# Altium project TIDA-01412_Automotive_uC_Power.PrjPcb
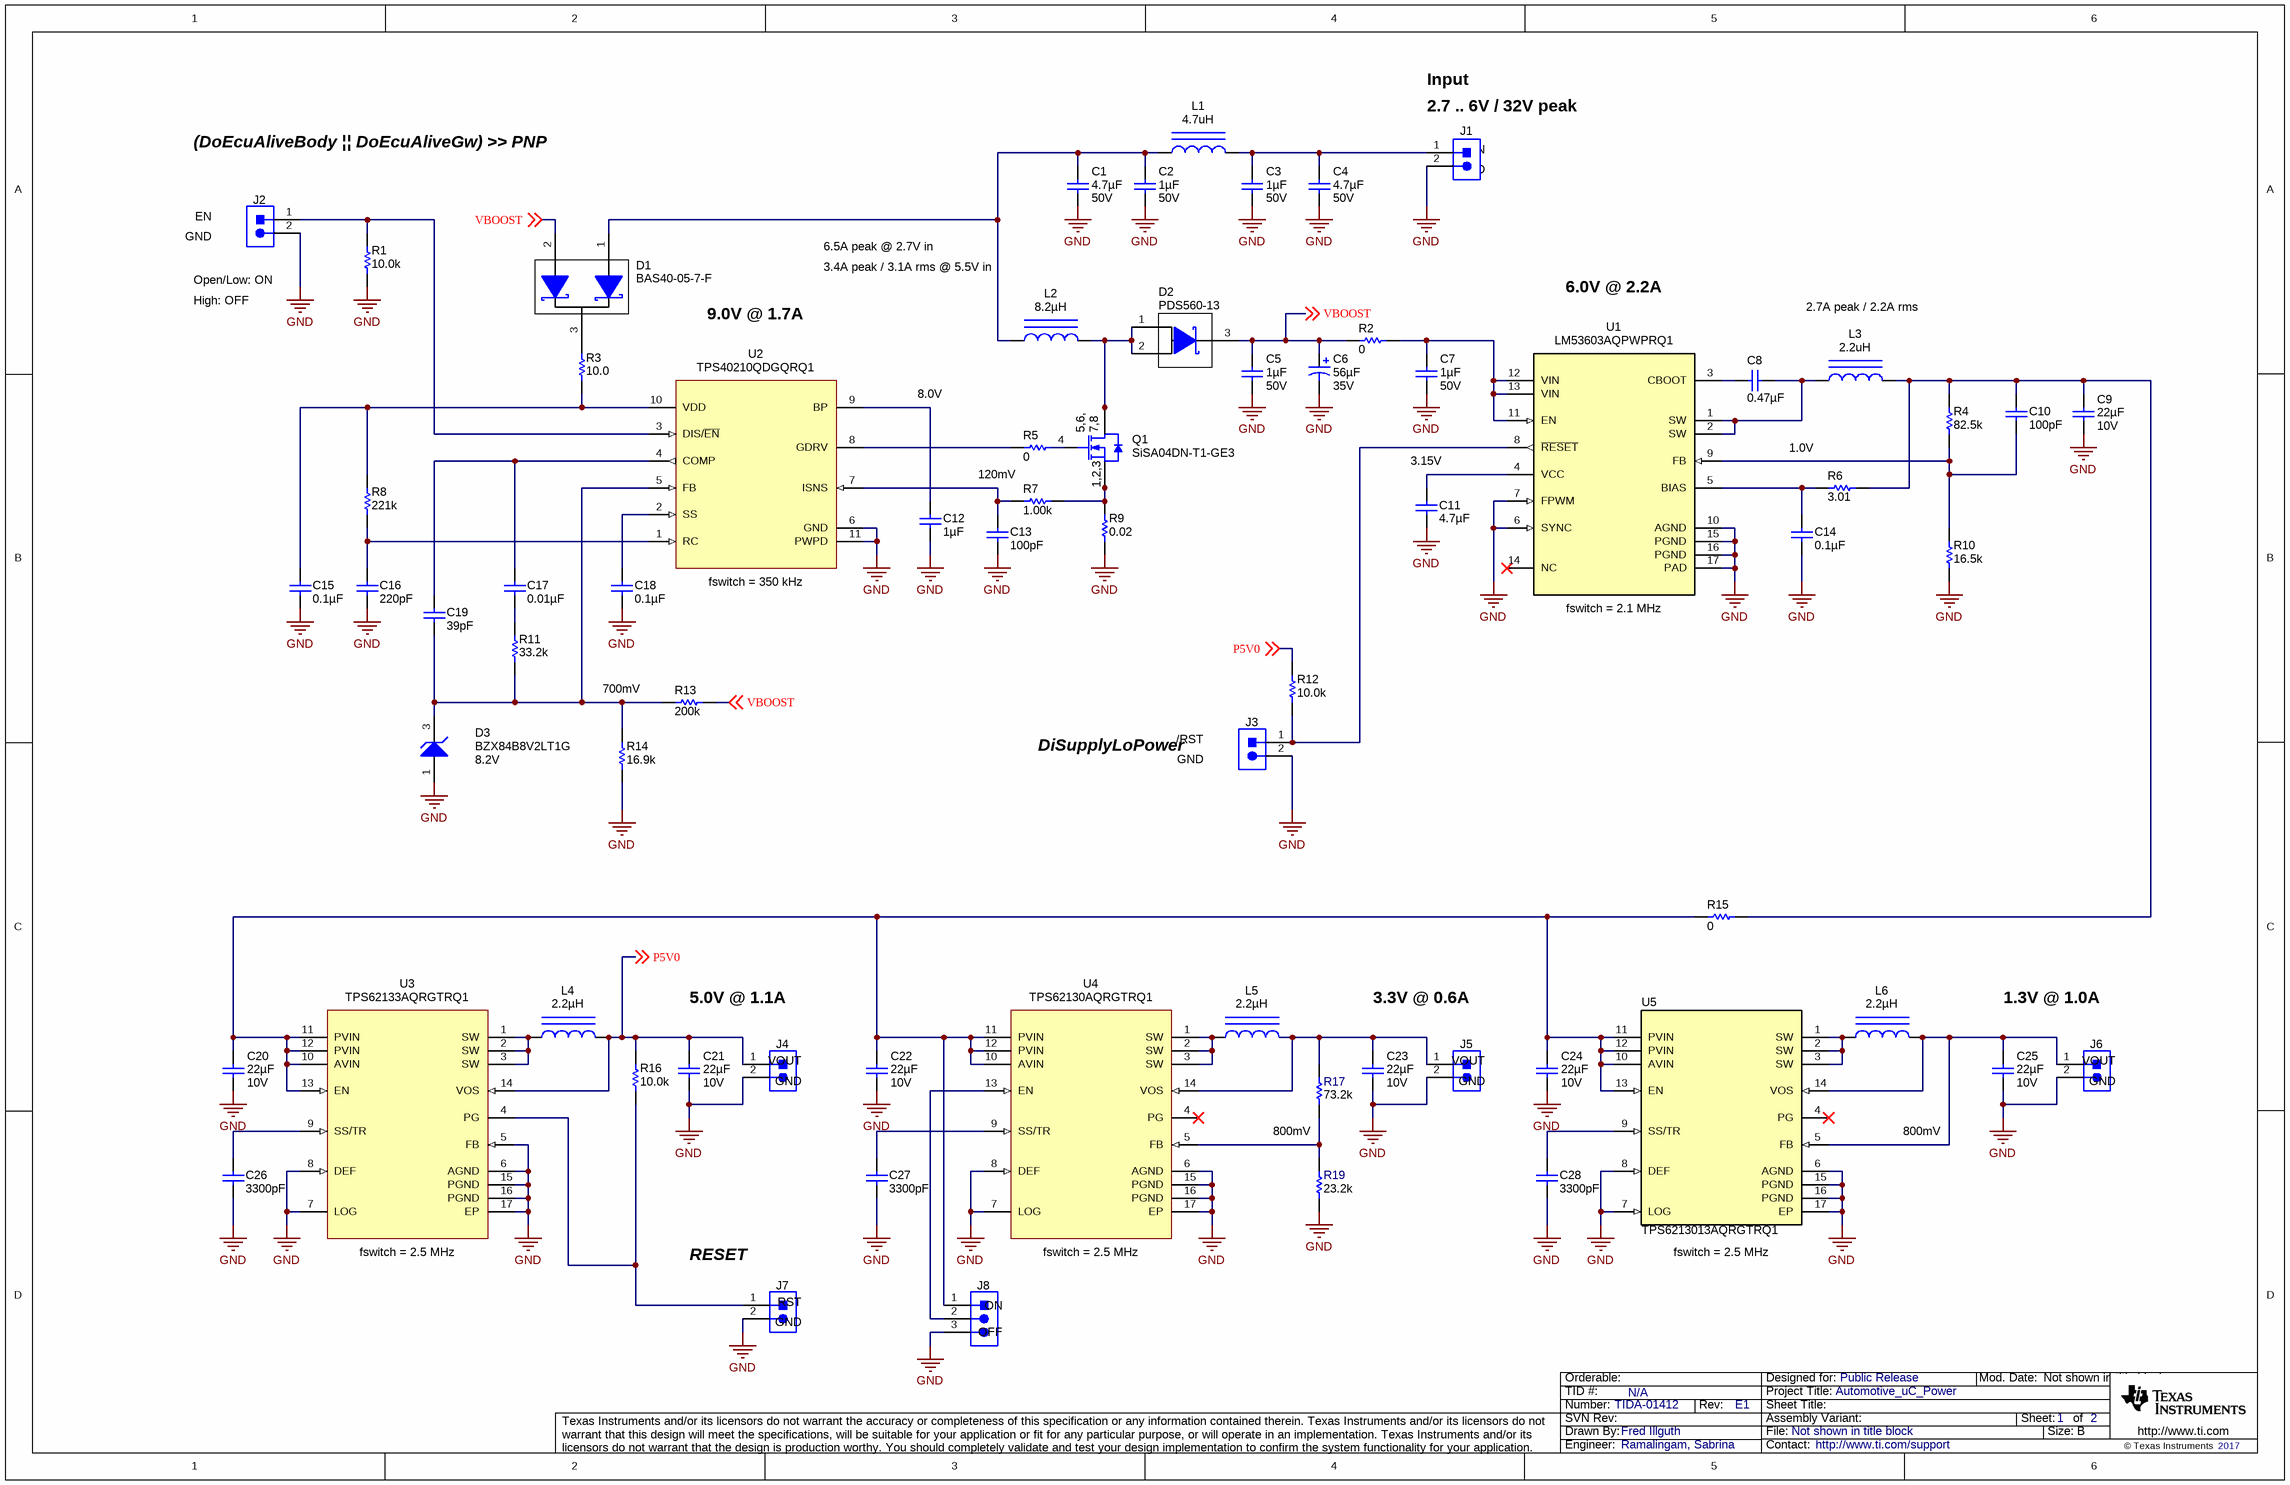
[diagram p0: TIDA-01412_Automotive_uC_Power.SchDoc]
CopyrightYear: 2017; PCB_Layout: Fred Illguth; PCB_Rev: E1; PRJ_Customer: Public Release; PRJ_Engineer: Ramalingam, Sabrina; PRJ_Number: TIDA-01412; PRJ_Title: Automotive_uC_Power; SCH_Rev: E1; TechSupport: http://www.ti.com/support; TID: N/A
2 sheets, 79 parts. Net scope: global (net labels, ports and power ports of the same name join across sheets).
Board file: TIDA-01412_Automotive_uC_Power.PcbDoc
Sheets:
  TIDA-01412_Automotive_uC_Power.SchDoc
  TIDA-01412_Automotive_uC_Power_Hardware.SchDoc

## Sheet TIDA-01412_Automotive_uC_Power.SchDoc
size 431 x 279 mm; Date: Not shown in title block; ApprovedBy: Not shown in title block; CheckedBy: Not shown in title block; Author: Not shown in title block; CompanyName: Not shown in title block; DrawnBy: Fred Illguth; Engineer: Not shown in title block; Organization: Not shown in title block; Address1: Not shown in title block; Address2: Not shown in title block; Address3: Not shown in title block; Address4: Not shown in title block; DocumentNumber: 1; Revision: Use project parameter SCH_Rev; SheetNumber: 1; SheetTotal: 2; PageSetup: Record=PageOptions¦CenterHorizontal=True¦CenterVertical=True¦PrintScale=1.00¦XCorrection=1.00¦YCorrection=1.00¦PrintKind=0¦BorderSize=5000000¦LeftOffset=0¦BottomOffset=0¦Orientation=2¦PaperLength=1000¦PaperWidth=1000¦Scale=100¦PaperSource=15¦PrintQuality=600¦MediaType=1¦DitherType=10¦PaperKind=Letter¦PrintScaleMode=1

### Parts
C1  ValueDisplayed: 4.7µF  Value2: 50V  [1210_270]  (hidden comment: GRM32ER71H475KA88L)
C2  ValueDisplayed: 1µF  Value2: 50V  [1206]  (hidden comment: GRM31MR71H105KA88L)
C3  ValueDisplayed: 1µF  Value2: 50V  [1206]  (hidden comment: GRM31MR71H105KA88L)
C4  ValueDisplayed: 4.7µF  Value2: 50V  [1210_270]  (hidden comment: GRM32ER71H475KA88L)
C5  ValueDisplayed: 1µF  Value2: 50V  [1206]  (hidden comment: GRM31MR71H105KA88L)
C6  ValueDisplayed: 56µF  Value2: 35V  [ZL_630x1100]  (hidden comment: 35ZL56MEFCTA6.3X11)
C7  ValueDisplayed: 1µF  Value2: 50V  [1206]  (hidden comment: GRM31MR71H105KA88L)
C8  ValueDisplayed: 0.47µF  [0603]  (hidden comment: GRM188R71E474KA12D)
C9  ValueDisplayed: 22µF  Value2: 10V  [1206_180]  (hidden comment: GCM31CR71A226KE02)
C10  ValueDisplayed: 100pF  [0603]  (hidden comment: GRM1885C1H101JA01D)
C11  ValueDisplayed: 4.7µF  [0805_HV]  (hidden comment: GRM21BR71A475KA73L)
C12  ValueDisplayed: 1µF  [0603]  (hidden comment: GRM188R71C105KA12D)
C13  ValueDisplayed: 100pF  [0603]  (hidden comment: GRM1885C1H101JA01D)
C14  ValueDisplayed: 0.1µF  [0603]  (hidden comment: GCM188R71H104KA57D)
C15  ValueDisplayed: 0.1µF  [0603]  (hidden comment: GCM188R71H104KA57D)
C16  ValueDisplayed: 220pF  [0603]  (hidden comment: GRM188R71H221KA01D)
C17  ValueDisplayed: 0.01µF  [0603]  (hidden comment: C0603X103K5RACTU)
C18  ValueDisplayed: 0.1µF  [0603]  (hidden comment: GCM188R71H104KA57D)
C19  ValueDisplayed: 39pF  [0603]  (hidden comment: GRM1885C1H390JA01D)
C20  ValueDisplayed: 22µF  Value2: 10V  [1206_180]  (hidden comment: GCM31CR71A226KE02)
C21  ValueDisplayed: 22µF  Value2: 10V  [1206_180]  (hidden comment: GCM31CR71A226KE02)
C22  ValueDisplayed: 22µF  Value2: 10V  [1206_180]  (hidden comment: GCM31CR71A226KE02)
C23  ValueDisplayed: 22µF  Value2: 10V  [1206_180]  (hidden comment: GCM31CR71A226KE02)
C24  ValueDisplayed: 22µF  Value2: 10V  [1206_180]  (hidden comment: GCM31CR71A226KE02)
C25  ValueDisplayed: 22µF  Value2: 10V  [1206_180]  (hidden comment: GCM31CR71A226KE02)
C26  ValueDisplayed: 3300pF  [0603]  (hidden comment: GRM188R71H332KA01D)
C27  ValueDisplayed: 3300pF  [0603]  (hidden comment: GRM188R71H332KA01D)
C28  ValueDisplayed: 3300pF  [0603]  (hidden comment: GRM188R71H332KA01D)
D1  BAS40-05-7-F  [SOT-23]
D2  PDS560-13  [PowerDI5]
D3  BZX84B8V2LT1G  value 8.2V  [SOT-23]
J1  ED555/2DS  [TERM_BLK_ED555-2DS]  (value not drawn)
J2  61300211121  [WURTH_61300211121]  (value not drawn)
J3  61300211121  [WURTH_61300211121]  (value not drawn)
J4  61300211121  [WURTH_61300211121]  (value not drawn)
J5  61300211121  [WURTH_61300211121]  (value not drawn)
J6  61300211121  [WURTH_61300211121]  (value not drawn)
J7  61300211121  [WURTH_61300211121]  (value not drawn)
J8  61300311121  [WURTH_61300311121]  (value not drawn)
L1  ValueDisplayed: 4.7uH  [B82477P4]  (hidden comment: B82464–G4472–M)
L2  ValueDisplayed: 8.2µH  [XAL6060]  (hidden comment: XAL6060-822MEB)
L3  ValueDisplayed: 2.2uH  [B82477P4]  (hidden comment: B82464–G4222–M)
L4  ValueDisplayed: 2.2µH  [VLF302510MT]  (hidden comment: VLF302510MT-2R2M)
L5  ValueDisplayed: 2.2µH  [VLF302510MT]  (hidden comment: VLF302510MT-2R2M)
L6  ValueDisplayed: 2.2µH  [VLF302510MT]  (hidden comment: VLF302510MT-2R2M)
Q1  SiSA04DN-T1-GE3  [PowerPAK_1212-8]
R1  ValueDisplayed: 10.0k  [0603]  (hidden comment: CRCW060310K0FKEA)
R2  ValueDisplayed: 0  [0603]  (hidden comment: CRCW06030000Z0EA)
R3  ValueDisplayed: 10.0  [0603]  (hidden comment: CRCW060310R0FKEA)
R4  ValueDisplayed: 82.5k  [0603]  (hidden comment: CRCW060382K5FKEA)
R5  ValueDisplayed: 0  [0603]  (hidden comment: CRCW06030000Z0EA)
R6  ValueDisplayed: 3.01  [0603]  (hidden comment: CRCW06033R01FKEA)
R7  ValueDisplayed: 1.00k  [0603]  (hidden comment: CRCW06031K00FKEA)
R8  ValueDisplayed: 221k  [0603]  (hidden comment: CRCW0603221KFKEA)
R9  ValueDisplayed: 0.02  [2010]  (hidden comment: WSL2010R0200FEA18)
R10  ValueDisplayed: 16.5k  [0603]  (hidden comment: CRCW060316K5FKEA)
R11  ValueDisplayed: 33.2k  [0603]  (hidden comment: CRCW060333K2FKEA)
R12  ValueDisplayed: 10.0k  [0603]  (hidden comment: CRCW060310K0FKEA)
R13  ValueDisplayed: 200k  [0603]  (hidden comment: CRCW0603200KFKEA)
R14  ValueDisplayed: 16.9k  [0603]  (hidden comment: CRCW060316K9FKEA)
R15  ValueDisplayed: 0  [0603]  (hidden comment: CRCW06030000Z0EA)
R16  ValueDisplayed: 10.0k  [0603]  (hidden comment: CRCW060310K0FKEA)
R17  ValueDisplayed: 73.2k  [0603]  (hidden comment: CRCW060373K2FKEA)
R19  ValueDisplayed: 23.2k  [0603]  (hidden comment: CRCW060323K2FKEA)
U1  LM53603AQPWPRQ1  [PWP0016H_N]
U2  TPS40210QDGQRQ1  [DGQ0010D_N]
U3  TPS62133AQRGTRQ1  [RGT0016C]
U4  TPS62130AQRGTRQ1  [RGT0016C]
U5  TPS6213013AQRGTRQ1  [RGT0016C]

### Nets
GND: C1.2 C2.2 C3.2 C4.2 C5.2 C6.2(-) C7.2 C9.2 C11.1 C12.2 C13.2 C14.2 C15.2 C16.2 C18.2 C20.2 C21.2 C22.2 C23.2 C24.2 C25.2 C26.2 C27.2 C28.2 D3.1(A) J1.2 J2.2 J3.2 J4.2 J5.2 J6.2 J7.2 J8.3 R1.1 R9.1 R10.1 R14.1 R19.1 U1.6(SYNC) U1.7(FPWM) U1.10(AGND) U1.15(PGND) U1.16(PGND) U1.17(PAD) U2.6(GND) U2.11(PWPD) U3.5(FB) U3.6(AGND) U3.7(LOG) U3.8(DEF) U3.15(PGND) U3.16(PGND) U3.17(EP) U4.6(AGND) U4.7(LOG) U4.8(DEF) U4.15(PGND) U4.16(PGND) U4.17(EP) U5.6(AGND) U5.7(LOG) U5.8(DEF) U5.15(PGND) U5.16(PGND) U5.17(EP)
P5V0: C21.1 J4.1 L4.2 R12.2 R16.2 U3.14(VOS) ; off-sheet P5V0
VBOOST: C5.1 C6.1(+) D1.2(A) D2.3(K) R2.1 R13.2 ; off-sheet VBOOST
NetC1_1: C1.1 C2.1 D1.1(A) L1.1 L2.1
NetC3_1: C3.1 C4.1 J1.1 L1.2
NetC7_1: C7.1 R2.2 U1.11(EN) U1.12(VIN) U1.13(VIN)
NetC8_1: C8.1 L3.1 U1.1(SW) U1.2(SW)
NetC8_2: C8.2 U1.3(CBOOT)
NetC9_1: C9.1 C10.1 L3.2 R4.2 R6.2 R15.2
NetC10_2: C10.2 R4.1 R10.2 U1.9(FB)
NetC11_2: C11.2 U1.4(VCC)
NetC12_1: C12.1 U2.9(BP)
NetC13_1: C13.1 R7.1 U2.7(ISNS)
NetC14_1: C14.1 R6.1 U1.5(BIAS)
NetC15_1: C15.1 R3.2 R8.2 U2.10(VDD)
NetC16_1: C16.1 R8.1 U2.1(RC)
NetC17_1: C17.1 C19.1 U2.4(COMP)
NetC17_2: C17.2 R11.2
NetC18_1: C18.1 U2.2(SS)
NetC19_2: C19.2 D3.3(K) R11.1 R13.1 R14.2 U2.5(FB)
NetC20_1: C20.1 C22.1 C24.1 J8.1 R15.1 U3.10(AVIN) U3.11(PVIN) U3.12(PVIN) U3.13(EN) U4.10(AVIN) U4.11(PVIN) U4.12(PVIN) U5.10(AVIN) U5.11(PVIN) U5.12(PVIN) U5.13(EN)
NetC23_1: C23.1 J5.1 L5.2 R17.2 U4.14(VOS)
NetC25_1: C25.1 J6.1 L6.2 U5.5(FB) U5.14(VOS)
NetC26_1: C26.1 U3.9(SS/TR)
NetC27_1: C27.1 U4.9(SS/TR)
NetC28_1: C28.1 U5.9(SS/TR)
NetD1_3: D1.3(K) R3.1
NetD2_1: D2.1(A) D2.2(A) L2.2 Q1.5(D) Q1.6(D) Q1.7(D) Q1.8(D) Q1.9(D)
NetJ2_1: J2.1 R1.2 U2.3(DIS/~{EN})
NetJ3_1: J3.1 R12.1 U1.8(~{RESET})
NetJ7_1: J7.1 R16.1 U3.4(PG)
NetJ8_2: J8.2 U4.13(EN)
NetL4_1: L4.1 U3.1(SW) U3.2(SW) U3.3(SW)
NetL5_1: L5.1 U4.1(SW) U4.2(SW) U4.3(SW)
NetL6_1: L6.1 U5.1(SW) U5.2(SW) U5.3(SW)
NetQ1_1: Q1.1(S) Q1.2(S) Q1.3(S) R7.2 R9.2
NetQ1_4: Q1.4(G) R5.2
NetR5_1: R5.1 U2.8(GDRV)
NetR17_1: R17.1 R19.2 U4.5(FB)

Not connected (* = marked no-connect by the designer): U1 14(NC)*; U4 4(PG)*; U5 4(PG)*

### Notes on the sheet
- Input
- (DoEcuAliveBody ¦¦ DoEcuAliveGw) >> PNP
- (near J1) 2.7 .. 6V / 32V peak
- (near J1) VIN
- (near J1) GND
- (near J2) EN
- (near J2) GND
- (near J2) Open/Low: ON
- High: OFF
- 6.5A peak @ 2.7V in
- 3.4A peak / 3.1A rms @ 5.5V in
- 6.0V @ 2.2A
- 2.7A peak / 2.2A rms
- 9.0V @ 1.7A
- 8.0V
- 120mV
- (near C11) 3.15V
- (near R6) 1.0V
- (near U2) fswitch = 350 kHz
- (near U1) fswitch = 2.1 MHz
- 700mV
- DiSupplyLoPower
- (near J3) /RST
- (near J3) GND
- 5.0V @ 1.1A
- 3.3V @ 0.6A
- 1.3V @ 1.0A
- VOUT
- (near J4) GND
- GND
- (near J6) VOUT
- (near J6) GND
- 800mV
- (near U3) fswitch = 2.5 MHz
- RESET
- (near J7) RST
- (near J8) ON
- (near U4) fswitch = 2.5 MHz
- (near U5) fswitch = 2.5 MHz
- (near J7) GND
- (near J8) OFF

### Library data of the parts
C1 C4 = GRM32ER71H475KA88L: CAP, CERM, 4.7 µF, 50 V, +/- 10%, X7R, 1210; Manufacturer: MuRata; Polarized: N; CompType: Capacitor; Value: 4.7uF; U/M: EA; Cap_F: 0.0000047; Tolerance_%: 10; ESR_ohm: 0.002; Value1: 0.002 ohm; VDC_V: 50; TaMin_C: -55; TaMax_C: 125; Cap_Case: 1210; SizeArea_mm2: 8; SizeAreaWB_mm2: 14.7; SizeX_mm: 3.2; SizeY_mm: 2.5; SizeZ_mm: 2.7; AEC Category: Q200
C2 C3 C5 C7 = GRM31MR71H105KA88L: CAP, CERM, 1 µF, 50 V, +/- 10%, X7R, 1206; Manufacturer: MuRata; Polarized: N; CompType: Capacitor; Value: 1uF; U/M: EA; Cap_F: 0.000001; Tolerance_%: 10; Value1: Unknown; VDC_V: 50; TaMin_C: -55; TaMax_C: 125; AEC Category: Q200
C6 = 35ZL56MEFCTA6.3X11: CAP, AL, 56 µF, 35 V, +/- 20%, 0.13 ohm, TH; Manufacturer: Rubycon; Polarized: Y; CompType: Capacitor; Value: 56uF; U/M: EA; Cap_F: 0.000056; Tolerance_%: 20; VDC_V: 35; ESR_ohm: 0.13; IRMS_A: 0.405; TaMin_C: -40; TaMax_C: 105; Cap_Case: 6.3x11
C8 = GRM188R71E474KA12D: CAP, CERM, 0.47 µF, 25 V, +/- 10%, X7R, 0603; Manufacturer: MuRata; Polarized: N; CompType: Capacitor; Value: 0.47uF; U/M: EA; Cap_F: 0.00000047; Tolerance_%: 10; Value1: Unknown; VDC_V: 25; Value2: 25V; TaMin_C: -55; TaMax_C: 125; AEC Category: Q200
C9 C20-C25 = GCM31CR71A226KE02: CAP, CERM, 22 µF, 10 V, +/- 10%, X7R, AEC-Q200 Grade 1, 1206; Manufacturer: MuRata; Polarized: N; CompType: Capacitor; Value: 22uF; U/M: EA; Cap_F: 0.000022; Tolerance_%: 10; Value1: Unknown; TaMin_C: -55; TaMax_C: 125; Cap_Case: 1206; SizeArea_mm2: 5.12; SizeAreaWB_mm2: 10.92; SizeX_mm: 3.2; SizeY_mm: 1.6; SizeZ_mm: 1.8; AEC Category: Q200; AEC Qualified: Y; AEC Grade: 1
C10 C13 = GRM1885C1H101JA01D: CAP, CERM, 100 pF, 50 V, +/- 5%, C0G/NP0, 0603; Manufacturer: MuRata; Polarized: N; CompType: Capacitor; Value: 100pF; U/M: EA; Cap_F: 0.0000000001; Tolerance_%: 5; Value1: Unknown; VDC_V: 50; Value2: 50V; TaMin_C: -55; TaMax_C: 125; AEC Category: Q200
C11 = GRM21BR71A475KA73L: CAP, CERM, 4.7 µF, 10 V, +/- 10%, X7R, 0805; Manufacturer: MuRata; Polarized: N; CompType: Capacitor; Value: 4.7uF; U/M: EA; Cap_F: 0.0000047; Tolerance_%: 10; Value1: Unknown; Value2: 10V; TaMin_C: -55; TaMax_C: 125; Cap_Case: 0805; AEC Category: Q200
C12 = GRM188R71C105KA12D: CAP, CERM, 1 µF, 16 V, +/- 10%, X7R, 0603; Manufacturer: MuRata; Polarized: N; CompType: Capacitor; Value: 1uF; U/M: EA; Cap_F: 0.000001; Tolerance_%: 10; ESR_ohm: 0.011; Value1: 0.011 ohm; VDC_V: 16; Value2: 16V; TaMin_C: -55; TaMax_C: 125; AEC Category: Q200
C14 C15 C18 = GCM188R71H104KA57D: CAP, CERM, 0.1 µF, 50 V, +/- 10%, X7R, 0603; Manufacturer: MuRata; Polarized: N; CompType: Capacitor; Value: 0.1uF; U/M: EA; Cap_F: 0.0000001; Tolerance_%: 10; ESR_ohm: 0.02; Value1: 0.02 ohm; VDC_V: 50; Value2: 50V; IRMS_A: 1.84; TaMin_C: -55; TaMax_C: 125; AEC Category: Q200
C16 = GRM188R71H221KA01D: CAP, CERM, 220 pF, 50 V, +/- 10%, X7R, 0603; Manufacturer: MuRata; Polarized: N; CompType: Capacitor; Value: 220pF; U/M: EA; Cap_F: 0.00000000022; Tolerance_%: 10; Value1: Unknown; VDC_V: 50; Value2: 50V; TaMin_C: -55; TaMax_C: 125; AEC Category: Q200
C17 = C0603X103K5RACTU: CAP, CERM, 0.01 µF, 50 V, +/- 10%, X7R, 0603; Manufacturer: Kemet; Polarized: N; CompType: Capacitor; Value: 0.01uF; U/M: EA; Cap_F: 0.00000001; Tolerance_%: 10; Value1: Unknown; VDC_V: 50; Value2: 50V; TaMin_C: -55; TaMax_C: 125; AEC Category: Q200
C19 = GRM1885C1H390JA01D: CAP, CERM, 39 pF, 50 V, +/- 5%, C0G/NP0, 0603; Manufacturer: MuRata; Polarized: N; CompType: Capacitor; Value: 39pF; U/M: EA; Cap_F: 0.000000000039; Tolerance_%: 5; Value1: Unknown; VDC_V: 50; Value2: 50V; TaMin_C: -55; TaMax_C: 125; AEC Category: Q200
C26-C28 = GRM188R71H332KA01D: CAP, CERM, 3300 pF, 50 V, +/- 10%, X7R, 0603; Manufacturer: MuRata; Polarized: N; CompType: Capacitor; Value: 3300pF; U/M: EA; Cap_F: 0.0000000033; Tolerance_%: 10; Value1: Unknown; VDC_V: 50; Value2: 50V; TaMin_C: -55; TaMax_C: 125; AEC Category: Q200
D1 = BAS40-05-7-F: Diode, Schottky, 40 V, 0.2 A, SOT-23; Manufacturer: Diodes Inc.; SymbolCreator: a0412235; U/M: EA; Vf_V: 0.9; Value: 40V; Value1: 0.2A; Value2: 0.9V; Io_A: 0.2; Vr_V: 40
D2 = PDS560-13: Diode, Schottky, 60 V, 5 A, PowerDI5; Manufacturer: Diodes Inc.; U/M: EA; Vf_V: 0.67; Value: 60V; Value1: 5A; Value2: 0.67V; Io_A: 5; Vr_V: 60; TJmax_C: 150
D3 = BZX84B8V2LT1G: Diode, Zener, 8.2 V, 225 mW, SOT-23; Manufacturer: ON Semiconductor; U/M: EA; Power_W: 0.225; Vz_V: 8.2; Value1: 0.225W; RJA_CperW: 556; SizeAreaWB_mm2: 14; SizeArea_mm2: 7.5; SizeX_mm: 2.5; SizeY_mm: 3; SizeZ_mm: 1.1; AEC Category: Q101
J1 = ED555/2DS: Terminal Block, 6A, 3.5mm Pitch, 2-Pos, TH; Manufacturer: On-Shore Technology; SymbolCreator: a0412235; CompType: Connector; U/M: EA
J2-J7 = 61300211121: Header, 2.54 mm, 2x1, Gold, TH; Manufacturer: Wurth Elektronik; SymbolCreator: a0412235; U/M: EA
J8 = 61300311121: Header, 2.54 mm, 3x1, Gold, TH; Manufacturer: Wurth Elektronik; SymbolCreator: a0799628; U/M: EA
L1 = B82477P4103M000: Inductor, Shielded, Ferrite, 4.7 µH, 4.9 A, 0.015 ohm, SMD; Manufacturer: TDK; Value: 4.7uH; Ind_H: 4.7E-6; Imax_A: 4.9; Irms: 4.9A @ 40C rise; Isat: 5.2A @ 10% inductance drop; DCR_ohm: 0.015; Value2: 4.9A
L2 = XAL6060-822MEB: Inductor, Shielded, Composite, 8.2 µH, 8.4 A, 0.02 ohm, SMD; Manufacturer: Coilcraft; Value: 8.2uH; Ind_H: 8.2E-6; Imax_A: 8.4; Irms: 9.4A @ 40C rise; Isat: 8.4A @ 30% inductance drop; DCR_ohm: 0.02; Value2: 8.4A; AEC Category: Q200
L3 = B82477P4103M000: Inductor, Shielded, Ferrite, 2.2 µH, 6.5 A, 0.01 ohm, SMD; Manufacturer: TDK; Value: 2.2uH; Ind_H: 2.2E-6; Imax_A: 6.5; Irms: 6.5A @ 40C rise; Isat: 7.0A @ 10% inductance drop; DCR_ohm: 0.010; Value2: 6.5A
L4-L6 = VLF302510MT-2R2M: Inductor, Shielded, Ferrite, 2.2 µH, 1.23 A, 0.084 ohm, SMD; Manufacturer: TDK; Value: 2.2uH; Ind_H: 2.2E-6; Imax_A: 1.23; Irms: 1.5A @ 40C rise; Isat: 1.23A @ 30% inductance drop; DCR_ohm: 0.084; Value2: 1.23A
Q1 = SiSA04DN-T1-GE3: MOSFET, N-CH, 30 V, 40 A, PowerPAK 1212; Manufacturer: Vishay-Siliconix; Alternate Manufacturer: None; U/M: EA; ChType: N; Value: 30V; VdsMax_V: 30; Value1: 0.0031 ohm; Rdson45_ohm: 0.0031; Value2: 22.5 nC; QgTyp_nC: 22.5; Vgs_V: 20; IdsMax_A: 40
R1 = CRCW060310K0FKEA: RES, 10.0 k, 1%, 0.1 W, 0603; Manufacturer: Vishay-Dale; CompType: Resistor; Value: 10.0k; Res_ohm: 10000; Value_Code: 10k0; Tolerance_%: 1; Power_W: 0.1; Value2: 0.1W; VDC_V: 75; TempCo: 100 ppm/C; EIA_Code: E96; U/M: EA
R2 R15 = CRCW06030000Z0EA: RES, 0, 5%, 0.1 W, 0603; Manufacturer: Vishay-Dale; CompType: Resistor; Value: 0; Value_Code: 0000; Tolerance_%: 5; Power_W: 0.1; Value2: 0.1W; VDC_V: 75; TempCo: 200 ppm/C; EIA_Code: E24; U/M: EA; AEC Category: Q200
R3 = CRCW060310R0FKEA: RES, 10.0, 1%, 0.1 W, 0603; Manufacturer: Vishay-Dale; CompType: Resistor; Value: 10.0; Res_ohm: 10; Value_Code: 10R0; Tolerance_%: 1; Power_W: 0.1; Value2: 0.1W; VDC_V: 75; TempCo: 100 ppm/C; EIA_Code: E96; U/M: EA
R4 = CRCW060382K5FKEA: RES, 82.5 k, 1%, 0.1 W, 0603; Manufacturer: Vishay-Dale; CompType: Resistor; Value: 82.5k; Res_ohm: 82500; Value_Code: 82k5; Tolerance_%: 1; Power_W: 0.1; Value2: 0.1W; VDC_V: 75; TempCo: 100 ppm/C; EIA_Code: E96; U/M: EA
R5 = CRCW06030000Z0EA: RES, 0, 5%, 0.1 W, 0603; Manufacturer: Vishay-Dale; CompType: Resistor; Value: 0; Value_Code: 0000; Tolerance_%: 5; Power_W: 0.1; Value2: 0.1W; VDC_V: 75; TempCo: 200 ppm/C; EIA_Code: E24; U/M: EA
R6 = CRCW06033R01FKEA: RES, 3.01, 1%, 0.1 W, 0603; Manufacturer: Vishay-Dale; CompType: Resistor; Value: 3.01; Value_Code: 3R01; Tolerance_%: 1; Power_W: 0.1; Value2: 0.1W; VDC_V: 75; TempCo: 100 ppm/C; EIA_Code: E96; U/M: EA
R7 = CRCW06031K00FKEA: RES, 1.00 k, 1%, 0.1 W, 0603; Manufacturer: Vishay-Dale; CompType: Resistor; Value: 1.00k; Res_ohm: 1000; Value_Code: 1k00; Tolerance_%: 1; Power_W: 0.1; Value2: 0.1W; VDC_V: 75; TempCo: 100 ppm/C; EIA_Code: E96; U/M: EA
R8 = CRCW0603221KFKEA: RES, 221 k, 1%, 0.1 W, 0603; Manufacturer: Vishay-Dale; CompType: Resistor; Value: 221k; Res_ohm: 221000; Tolerance_%: 1; Power_W: 0.1; Value2: 0.1W; VDC_V: 75; TempCo: 100 ppm/C; EIA_Code: E96; U/M: EA
R9 = WSL2010R0200FEA18: RES, 0.02, 1%, 1 W, 2010; Manufacturer: Vishay-Dale; CompType: Resistor; Value: 0.02; Value_Code: R020; Tolerance_%: 1; Value2: 1W; TempCo: 75 ppm/C; EIA_Code: E96; U/M: EA
R10 = CRCW060316K5FKEA: RES, 16.5 k, 1%, 0.1 W, 0603; Manufacturer: Vishay-Dale; CompType: Resistor; Value: 16.5k; Res_ohm: 16500; Value_Code: 16k5; Tolerance_%: 1; Power_W: 0.1; Value2: 0.1W; VDC_V: 75; TempCo: 100 ppm/C; EIA_Code: E96; U/M: EA
R11 = CRCW060333K2FKEA: RES, 33.2 k, 1%, 0.1 W, 0603; Manufacturer: Vishay-Dale; CompType: Resistor; Value: 33.2k; Res_ohm: 33200; Value_Code: 33k2; Tolerance_%: 1; Power_W: 0.1; Value2: 0.1W; VDC_V: 75; TempCo: 100 ppm/C; EIA_Code: E96; U/M: EA
R12 R16 = CRCW060310K0FKEA: RES, 10.0 k, 1%, 0.1 W, 0603; Manufacturer: Vishay-Dale; CompType: Resistor; Value: 10.0k; Res_ohm: 10000; Value_Code: 10k0; Tolerance_%: 1; Power_W: 0.1; Value2: 0.1W; VDC_V: 75; TempCo: 100 ppm/C; EIA_Code: E96; U/M: EA; AEC Category: Q200
R13 = CRCW0603200KFKEA: RES, 200 k, 1%, 0.1 W, 0603; Manufacturer: Vishay-Dale; CompType: Resistor; Value: 200k; Res_ohm: 200000; Tolerance_%: 1; Power_W: 0.1; Value2: 0.1W; VDC_V: 75; TempCo: 100 ppm/C; EIA_Code: E96; U/M: EA
R14 = CRCW060316K9FKEA: RES, 16.9 k, 1%, 0.1 W, 0603; Manufacturer: Vishay-Dale; CompType: Resistor; Value: 16.9k; Res_ohm: 16900; Value_Code: 16k9; Tolerance_%: 1; Power_W: 0.1; Value2: 0.1W; VDC_V: 75; TempCo: 100 ppm/C; EIA_Code: E96; U/M: EA; AEC Category: Q200
R17 = CRCW060373K2FKEA: RES, 73.2 k, 1%, 0.1 W, 0603; Manufacturer: Vishay-Dale; CompType: Resistor; Value: 73.2k; Res_ohm: 73200; Value_Code: 73k2; Tolerance_%: 1; Power_W: 0.1; Value2: 0.1W; VDC_V: 75; TempCo: 100 ppm/C; EIA_Code: E96; U/M: EA
R19 = CRCW060323K2FKEA: RES, 23.2 k, 1%, 0.1 W, 0603; Manufacturer: Vishay-Dale; CompType: Resistor; Value: 23.2k; Res_ohm: 23200; Value_Code: 23k2; Tolerance_%: 1; Power_W: 0.1; Value2: 0.1W; VDC_V: 75; TempCo: 100 ppm/C; EIA_Code: E96; U/M: EA
U1 = LM53603AQPWPRQ1: 5V/3.3V/ADJ, 3A, Buck Regulator For Automotive Applications, PWP0016H; Alternate PartNumber: LM53603AQPWPTQ1; Manufacturer: Texas Instruments; SymbolCreator: Altium; CompType: IC; U/M: EA
U2 = TPS40210QDGQRQ1: 4.5-V TO 52-V INPUT CURRENT MODE BOOST CONTROLLER, DGQ0010D; Manufacturer: Texas Instruments; SymbolCreator: a0412235; CompType: IC; U/M: EA
U3 = TPS62133AQRGTRQ1: 3V to 17-V 3A Step-Down Converter with DCS-Control™, RGT0016C; Alternate PartNumber: TPS62133AQRGTTQ1; Manufacturer: Texas Instruments; SymbolCreator: Altium; CompType: IC; U/M: EA
U4 = TPS62130AQRGTRQ1: 3V to 17-V 3A Step-Down Converter with DCS-Control™, RGT0016C; Alternate PartNumber: TPS62130AQRGTTQ1; Manufacturer: Texas Instruments; SymbolCreator: Altium; CompType: IC; U/M: EA
U5 = TPS6213013AQRGTRQ1: 3V-17V 3A Step-Down Converter With DCS-Control, RGT0016C (VQFN-16); Alternate PartNumber: TPS6213013AQRGTTQ1; Manufacturer: Texas Instruments; SymbolCreator: a0411947; SizeArea_mm2: 16; SizeAreaWB_mm2: 25; SizeX_mm: 4; SizeZ_mm: 1; CompType: IC; U/M: EA

## Sheet TIDA-01412_Automotive_uC_Power_Hardware.SchDoc
size 431 x 279 mm; Date: Not shown in title block; ApprovedBy: Not shown in title block; CheckedBy: Not shown in title block; Author: Not shown in title block; CompanyName: Not shown in title block; DrawnBy: Fred Illguth; Engineer: Not shown in title block; Organization: Not shown in title block; Address1: Not shown in title block; Address2: Not shown in title block; Address3: Not shown in title block; Address4: Not shown in title block; DocumentNumber: 2; Revision: Use project parameter SCH_Rev; SheetNumber: 2; SheetTotal: 2; PageSetup: Record=PageOptions¦CenterHorizontal=True¦CenterVertical=True¦PrintScale=1.00¦XCorrection=1.00¦YCorrection=1.00¦PrintKind=0¦BorderSize=5000000¦LeftOffset=0¦BottomOffset=0¦Orientation=2¦PaperLength=1000¦PaperWidth=1000¦Scale=100¦PaperSource=15¦PrintQuality=600¦MediaType=1¦DitherType=10¦PaperKind=Letter¦PrintScaleMode=1
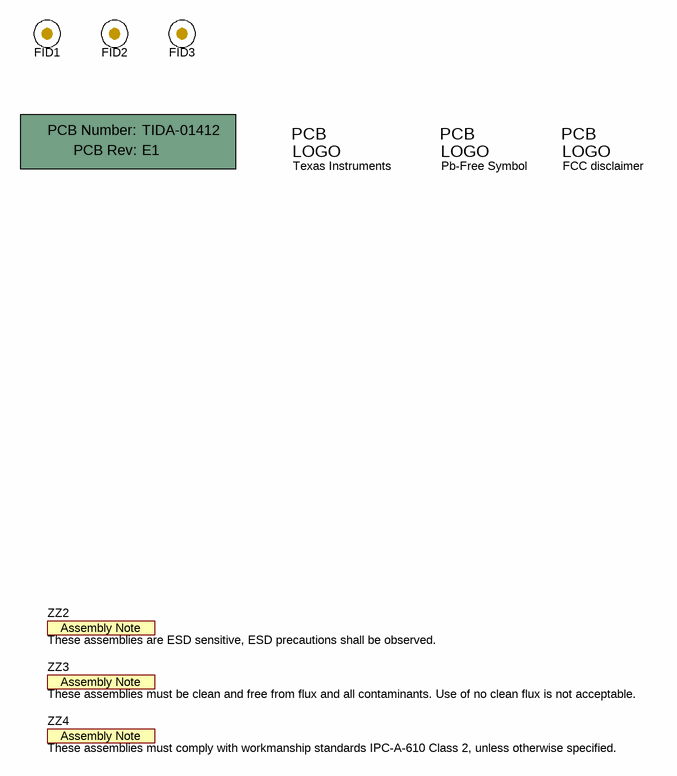
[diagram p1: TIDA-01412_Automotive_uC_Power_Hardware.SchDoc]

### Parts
!PCB  Printed Circuit Board  (value not drawn)  (mechanical)
FID1  Fiducial  [Fiducial10-20]  (value not drawn)
FID2  Fiducial  [Fiducial10-20]  (value not drawn)
FID3  Fiducial  [Fiducial10-20]  (value not drawn)
Logo1  Texas Instruments  [TI_Symbol_Overlay_Small]  (no BOM)
Logo2  Pb-Free Symbol  [Pb-Free_Overlay_Small]  (no BOM)
Logo3  FCC disclaimer  [FCC_disclaimer]  (no BOM)
ZZ2  These assemblies are ESD sensitive, ESD precautions shall be observed.  [AssemblyNote]  (no BOM)
ZZ3  These assemblies must be clean and free from flux and all contaminants. Use of no clean flux is not acceptable.  [AssemblyNote]  (no BOM)
ZZ4  These assemblies must comply with workmanship standards IPC-A-610 Class 2, unless otherwise specified.  [AssemblyNote]  (no BOM)

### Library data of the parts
!PCB = PCB: Manufacturer: Any; PartNumber: TIDA-01412; SymbolCreator: a0412235
FID1-FID3 = Fiducial: Fiducial mark.  There is nothing to buy or mount.; SymbolCreator: codlsc
Logo1 = TI_Logo: Texas Instrument Corporate Signature; SymbolCreator: codlsc
Logo2 = Pb-Free: SymbolCreator: a0412235
Logo3 = FCC_disclaimer: SymbolCreator: codlsc
ZZ2-ZZ4 = AssemblyNote: SymbolCreator: codlsc

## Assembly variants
001: not fitted FID1 FID2 FID3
